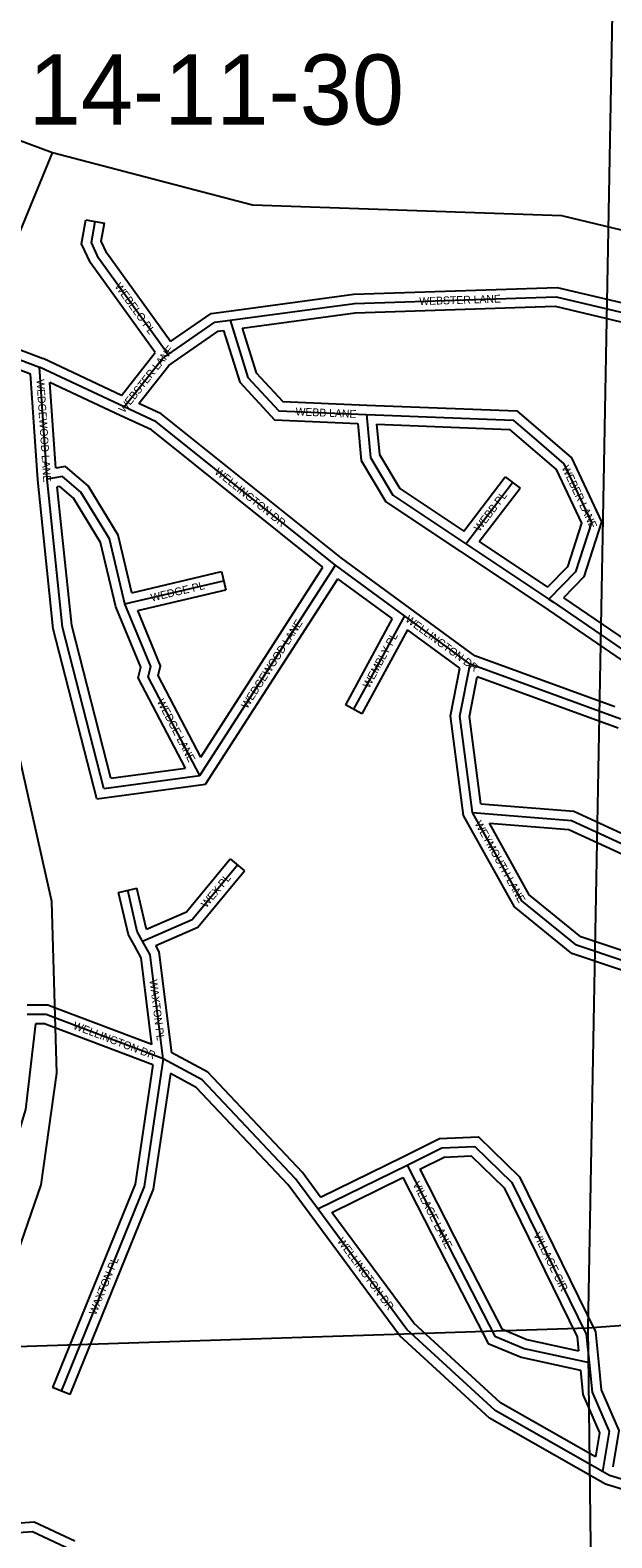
# Model space of a CAD drawing. Extents: x 457167 to 656239, y 1787309 to 1969297.
# Drawn here: x 578066 to 579932, y 1892149 to 1896984 of the extents above; entities that cross this region are included whole.
import ezdxf

# ---------------------------------------------------------------- set-up
doc = ezdxf.new("R2010")
doc.units = 0
for name, color, linetype in [('Level 1', 7, 'Continuous'), ('Level 2', 7, 'Continuous'), ('Level 31', 7, 'Continuous'), ('Level 32', 7, 'Continuous'), ('Level 34', 7, 'Continuous'), ('Level 5', 7, 'Continuous')]:
    doc.layers.add(name, color=color, linetype=linetype)

msp = doc.modelspace()

# ---------------------------------------------------------------- linework, layer by layer
at = {"layer": 'Level 1'}
for p, q in [((579953.491, 1898090.679), (579855.256, 1892821.831)), ((579855.256, 1892821.831), (585080.121, 1893221.401)), ((576739.189, 1892721.021), (579855.256, 1892821.831)), ((579855.256, 1892821.831), (579922.889, 1887536.016))]:
    msp.add_line(p, q, dxfattribs=at)
at = {"layer": 'Level 31'}
for p, q in [((578120.434, 1895544.188), (578096.068, 1895902.789)), ((578367.986, 1895775.306), (578096.068, 1895902.789)), ((579463.774, 1895336.65), (579613.948, 1895533.068)), ((579463.774, 1895336.65), (579730.51, 1895159.004)), ((578610.677, 1894593.328), (579045.49, 1895267.7)), ((579266.785, 1895105.419), (579045.49, 1895267.7)), ((578369.843, 1895143.658), (578686.706, 1895218.266)), ((579730.51, 1895159.004), (579744.799, 1895149.156)), ((579744.799, 1895149.156), (580021.054, 1894960.221)), ((579266.785, 1895105.419), (579103.994, 1894806.118)), ((579478.24, 1894950.432), (579266.785, 1895105.419)), ((579961.529, 1894774.523), (579478.24, 1894950.432)), ((578302.145, 1894552.157), (578610.677, 1894593.328)), ((578492.713, 1893684.837), (578145.742, 1893816.477)), ((578988.735, 1893203.794), (579275.224, 1893344.291))]:
    msp.add_line(p, q, dxfattribs=at)
for points in [[(578509.2, 1895943.375), (578285.678, 1896252.94), (578262.571, 1896302.807), (578274.795, 1896370.419)], [(578707.526, 1896053.143), (579106.694, 1896107.583), (579753.809, 1896128.422), (579980.414, 1896074.863)], [(578509.2, 1895943.375), (578658.228, 1896046.7), (578707.526, 1896053.143)], [(578707.526, 1896053.143), (578765.015, 1895869.747), (578863.684, 1895762.994), (579144.749, 1895751.499)], [(577895.856, 1895955.577), (577962.624, 1895952.89), (578096.068, 1895902.789)], [(578367.986, 1895775.306), (578490.414, 1895930.687), (578509.2, 1895943.375)], [(579045.49, 1895267.7), (578470.909, 1895727.09), (578367.986, 1895775.306)], [(579144.749, 1895751.499), (579615.631, 1895733.067), (579698.476, 1895661.986)], [(579144.749, 1895751.499), (579157.818, 1895613.652), (579230.065, 1895492.41), (579463.774, 1895336.65)], [(579698.476, 1895661.986), (579778.465, 1895593.456), (579867.429, 1895404.543), (579816.228, 1895246.465), (579730.51, 1895159.004)], [(578369.843, 1895143.658), (578320.357, 1895352.128), (578228.776, 1895502.505), (578170.374, 1895552.446), (578120.434, 1895544.188)], [(578302.145, 1894552.157), (578169.677, 1895069.17), (578120.434, 1895544.188)], [(578610.677, 1894593.328), (578444.398, 1894910.408), (578453.053, 1894943.481), (578369.843, 1895143.658)], [(579485.844, 1894475.139), (579444.826, 1894783.591), (579478.24, 1894950.432)], [(579485.844, 1894475.139), (579802.505, 1894449.393), (580094.143, 1894315.7), (580192.375, 1894303.134)], [(580702.275, 1894072.271), (580518.912, 1893973.371), (580385.289, 1893940.189), (580118.513, 1893948.736), (579818.537, 1894049.355), (579643.935, 1894191.536), (579485.844, 1894475.139)], [(578426.725, 1894062.798), (578585.864, 1894131.92), (578730.914, 1894306.891)], [(578426.725, 1894062.798), (578409.936, 1894093.38), (578379.049, 1894225.446)], [(578492.713, 1893684.837), (578451.436, 1894018.382), (578426.725, 1894062.798)], [(578145.742, 1893816.477), (578117.78, 1893827.082), (578056.09, 1893827.212)], [(578492.713, 1893684.837), (578431.755, 1893275.506), (578165.488, 1892619.696)], [(578988.735, 1893203.794), (578917.07, 1893300.672), (578617.544, 1893617.666), (578492.713, 1893684.837)], [(579275.224, 1893344.291), (579387.272, 1893399.331), (579492.539, 1893404.204), (579611.548, 1893288.683), (579850.317, 1892801.639), (579859.67, 1892710.711)], [(579275.224, 1893344.291), (579427.883, 1893046.516), (579557.425, 1892795.335), (579650.838, 1892756.596), (579859.67, 1892710.711)], [(579902.519, 1892361.164), (579557.889, 1892557.514), (579274.768, 1892816.649), (578988.735, 1893203.794)], [(579859.67, 1892710.711), (579869.017, 1892616.508), (579923.452, 1892489.486), (579902.519, 1892361.164)], [(580224.125, 1892256.501), (579924.435, 1892348.755), (579902.519, 1892361.164)], [(578196.539, 1892110.896), (578073.273, 1892168.248), (577614.957, 1892135.4)]]:
    msp.add_lwpolyline(points, dxfattribs=at)
at = {"layer": 'Level 32'}
for p, q in [((578245.274, 1896375.757), (578304.318, 1896365.081)), ((578359.16, 1895812.578), (578107.726, 1895930.456)), ((578359.161, 1895812.578), (578467.424, 1895949.985)), ((578090.539, 1895541.623), (578067.446, 1895881.489)), ((578148.128, 1895579.175), (578129.453, 1895854.002)), ((578355.253, 1895748.142), (578129.453, 1895854.002)), ((579457.019, 1895377.205), (579590.115, 1895551.29)), ((579590.115, 1895551.29), (579637.78, 1895514.846)), ((579507.059, 1895343.867), (579637.78, 1895514.846)), ((579507.059, 1895343.867), (579726.469, 1895197.741)), ((579447.145, 1895311.679), (579713.882, 1895134.033)), ((578392.117, 1895179.722), (578679.831, 1895247.468)), ((578613.349, 1894652.831), (579005.595, 1895261.186)), ((578679.831, 1895247.468), (578693.583, 1895189.064)), ((579284.527, 1895129.611), (579063.736, 1895291.521)), ((578628.382, 1894565.423), (579053.44, 1895224.666)), ((579227.907, 1895096.726), (579053.44, 1895224.666)), ((578411.105, 1895122.552), (578693.583, 1895189.064)), ((579776.944, 1895163.518), (580004.732, 1895007.73)), ((579492.523, 1894977.159), (579284.52, 1895129.615)), ((579713.882, 1895134.033), (579727.775, 1895124.454)), ((579727.864, 1895124.392), (579985.66, 1894948.082)), ((579227.907, 1895096.726), (579077.64, 1894820.452)), ((579276.739, 1895060.926), (579130.349, 1894791.783)), ((579445.065, 1894937.552), (579276.739, 1895060.927)), ((579942.484, 1894813.381), (579492.524, 1894977.159)), ((579953.204, 1894745.626), (579500.799, 1894910.295)), ((579130.349, 1894791.783), (579077.64, 1894820.452)), ((578324.593, 1894585.418), (578564.184, 1894617.389)), ((578279.699, 1894518.894), (578628.382, 1894565.423)), ((578707.818, 1894326.038), (578754.01, 1894287.744)), ((578349.838, 1894218.614), (578408.261, 1894232.278)), ((578456.829, 1893730.538), (578156.384, 1893844.526)), ((578459.481, 1893665.357), (578135.1, 1893788.427)), ((578997.982, 1893241.741), (579262.014, 1893371.226)), ((579034.237, 1893192.693), (579261.973, 1893304.376)), ((578193.284, 1892608.41), (578137.691, 1892630.981))]:
    msp.add_line(p, q, dxfattribs=at)
for points in [[(578467.424, 1895949.985), (578259.669, 1896237.712), (578231.361, 1896298.806), (578245.274, 1896375.757)], [(578516.294, 1895984.798), (578311.688, 1896268.166), (578293.782, 1896306.809), (578304.318, 1896365.081)], [(578703.472, 1896082.868), (579104.178, 1896137.518), (579756.829, 1896158.536), (579999.101, 1896101.273)], [(578516.294, 1895984.798), (578647.119, 1896075.504), (578703.639, 1896082.89)], [(578746.781, 1896028.217), (579109.212, 1896077.648), (579750.79, 1896098.309), (579961.728, 1896048.451)], [(578526.294, 1895918.72), (578669.336, 1896017.896), (578686.436, 1896020.13)], [(578686.436, 1896020.131), (578738.406, 1895854.337), (578850.069, 1895733.525), (579117.354, 1895722.593)], [(578746.78, 1896028.216), (578791.625, 1895885.156), (578877.298, 1895792.463), (579145.974, 1895781.474)], [(577897.062, 1895985.554), (577968.651, 1895982.672), (578107.727, 1895930.456)], [(577894.649, 1895925.601), (577956.597, 1895923.107), (578067.447, 1895881.49)], [(578414.949, 1895786.434), (578511.083, 1895908.444), (578526.294, 1895918.72)], [(579063.735, 1895291.521), (578486.862, 1895752.746), (578414.95, 1895786.433)], [(579145.922, 1895781.476), (579627.24, 1895762.636), (579718.011, 1895684.754)], [(579005.595, 1895261.186), (578454.957, 1895701.433), (578355.26, 1895748.139)], [(579117.354, 1895722.592), (579128.589, 1895604.096), (579207.773, 1895471.214), (579447.137, 1895311.686)], [(579177.854, 1895720.178), (579604.023, 1895703.498), (579678.941, 1895639.218)], [(579177.854, 1895720.178), (579187.046, 1895623.207), (579252.358, 1895513.605), (579457.019, 1895377.205)], [(579717.994, 1895684.769), (579802.867, 1895612.055), (579899.625, 1895406.588), (579842.593, 1895230.506), (579776.944, 1895163.518)], [(579678.958, 1895639.203), (579754.064, 1895574.856), (579835.231, 1895402.498), (579789.862, 1895262.423), (579726.469, 1895197.74)], [(578392.116, 1895179.723), (578348.45, 1895363.676), (578251.91, 1895522.196), (578179.258, 1895584.324), (578148.128, 1895579.174)], [(578279.699, 1894518.894), (578140.065, 1895063.871), (578090.539, 1895541.623)], [(578341.214, 1895134.376), (578292.264, 1895340.579), (578205.642, 1895482.813), (578161.49, 1895520.569), (578153.187, 1895519.196)], [(578324.593, 1894585.418), (578199.289, 1895074.468), (578153.188, 1895519.196)], [(578564.184, 1894617.39), (578412.434, 1894906.765), (578421.47, 1894941.298), (578341.214, 1895134.376)], [(578613.349, 1894652.831), (578476.363, 1894914.051), (578484.634, 1894945.663), (578411.106, 1895122.551)], [(579456.86, 1894465.52), (579414.429, 1894784.586), (579445.065, 1894937.552)], [(579512.394, 1894503.08), (579475.223, 1894782.596), (579500.799, 1894910.294)], [(579512.394, 1894503.079), (579810.204, 1894478.867), (580102.486, 1894344.878), (580172.647, 1894335.902)], [(580729.723, 1894052.986), (580529.819, 1893945.167), (580388.484, 1893910.071), (580113.149, 1893918.893), (579803.824, 1894022.647), (579620.532, 1894171.905), (579456.86, 1894465.52)], [(579539.398, 1894440.684), (579794.807, 1894419.919), (580085.799, 1894286.521), (580188.569, 1894273.376)], [(580674.829, 1894091.552), (580508.005, 1894001.573), (580382.094, 1893970.307), (580123.877, 1893978.581), (579833.249, 1894076.063), (579667.339, 1894211.167), (579539.398, 1894440.684)], [(578439.861, 1894101.211), (578567.34, 1894156.583), (578707.818, 1894326.038)], [(578469.031, 1894048.464), (578604.389, 1894107.257), (578754.01, 1894287.744)], [(578439.861, 1894101.211), (578438.212, 1894104.214), (578408.261, 1894232.278)], [(578400.428, 1894048.361), (578381.659, 1894082.546), (578349.838, 1894218.614)], [(578456.828, 1893730.539), (578422.379, 1894008.901), (578400.509, 1894048.213)], [(578520.583, 1893703.907), (578480.492, 1894027.863), (578469.031, 1894048.464)], [(578156.38, 1893844.528), (578123.309, 1893857.071), (578056.154, 1893857.213)], [(578082.804, 1893797.154), (578050.933, 1893522.652), (578002.139, 1893359.858)], [(578135.103, 1893788.426), (578112.252, 1893797.093), (578082.804, 1893797.155)], [(578997.981, 1893241.741), (578940.115, 1893319.966), (578636.024, 1893641.79), (578520.583, 1893703.907)], [(578459.481, 1893665.357), (578402.609, 1893283.471), (578137.691, 1892630.981)], [(578516.098, 1893638.185), (578460.901, 1893267.541), (578193.284, 1892608.41)], [(578964.617, 1893185.952), (578894.025, 1893281.379), (578599.064, 1893593.542), (578516.098, 1893638.185)], [(579261.996, 1893371.217), (579379.648, 1893429.011), (579504.119, 1893434.773), (579636.188, 1893306.576), (579879.612, 1892810.036), (579889.513, 1892713.78)], [(579315.844, 1893330.818), (579394.895, 1893369.651), (579480.958, 1893373.635), (579586.908, 1893270.791), (579821.022, 1892793.242), (579825.581, 1892748.916)], [(579315.844, 1893330.818), (579454.563, 1893060.234), (579579.057, 1892818.842), (579659.874, 1892785.327), (579825.581, 1892748.916)], [(579261.973, 1893304.376), (579401.203, 1893032.796), (579535.794, 1892771.828), (579641.803, 1892727.866), (579831.968, 1892686.081)], [(579887.668, 1892335.097), (579540.115, 1892533.112), (579252.367, 1892796.483), (578964.606, 1893185.966)], [(579879.861, 1892408.601), (579575.664, 1892581.915), (579297.169, 1892836.816), (579034.237, 1893192.693)], [(579831.967, 1892686.081), (579839.62, 1892608.943), (579892.437, 1892485.696), (579879.861, 1892408.601)], [(579889.524, 1892713.672), (579898.414, 1892624.074), (579954.468, 1892493.275), (579935.494, 1892376.969)], [(580192.379, 1892234.883), (579912.493, 1892321.041), (579887.738, 1892335.057)], [(578209.193, 1892138.097), (578078.88, 1892198.728), (577631.747, 1892166.68)]]:
    msp.add_lwpolyline(points, dxfattribs=at)
at = {"layer": 'Level 5'}
for points in [[(578138.009, 1896589.983), (577213.032, 1896932.786), (576748.308, 1896983.071)], [(576740.565, 1891623.016), (577149.298, 1891880.984), (577708.418, 1892430.6), (577950.616, 1892847.151), (578101.122, 1893280.483), (578151.529, 1893638.911), (578135.441, 1894189.115), (577861.641, 1895406.513), (577870.307, 1895706.62), (577903.974, 1896023.368), (578138.009, 1896589.983)], [(584831.26, 1895849.23), (584764.372, 1895682.606), (584505.692, 1895416.097), (584288.751, 1895249.602), (584163.64, 1895191.381), (583905.246, 1895208.339), (582955.14, 1895434.44), (582579.975, 1895409.817), (582438.224, 1895359.966), (582254.565, 1895126.739), (582120.867, 1894810.091), (582012.368, 1894693.517), (581912.326, 1894693.616), (581737.333, 1894768.837), (581254.577, 1895461.241), (580963.159, 1895786.688), (580654.941, 1896028.772), (580155.06, 1896296.056), (579771.684, 1896388.176), (578779.7, 1896422.572), (578138.009, 1896589.983)]]:
    msp.add_lwpolyline(points, dxfattribs=at)

# ---------------------------------------------------------------- texts
at = {"layer": 'Level 2'}
msp.add_text('14-11-30', height=225, dxfattribs=at).set_placement((578061.214, 1896680.654))
at = {"layer": 'Level 34'}
for s, height, rotation, p in [('WEBELO PL', 25, 305.830947, (578335.864, 1896162.083)), ('WEBSTER LANE', 25, 1.844222, (579314.966, 1896101.784)), ('WEBSTER LANE', 25, 51.763992, (578367.381, 1895754.344)), ('WEDGEWOOD LANE', 25, 273.886464, (578086.237, 1895863.106)), ('WEBB LANE', 25, 357.657675, (578917.321, 1895748.291)), ('WELLINGTON DR', 25, 321.356747, (578655.929, 1895563.158)), ('WEBER LANE', 25, 295.216314, (579770.779, 1895580.441)), ('WEBB PL', 25, 52.599275, (579507.757, 1895373.597)), ('WEDGE PL', 25, 13.249078, (578456.181, 1895151.146)), ('WELLINGTON DR', 25, 323.760231, (579267.575, 1895089.342)), ('WEDGEWOOD LANE', 25, 57.186489, (578762.294, 1894805.417)), ('WEMBLY PL', 25, 61.457192, (579153.706, 1894871.357)), ('WEDGE LANE', 24.9992, 297.672367, (578471.929, 1894830.996)), ('WEYMOUTH LANE', 25, 299.136483, (579491.174, 1894439.907)), ('WEX PL', 25, 50.340664, (578631.227, 1894167.055)), ('WAXTON PL', 24.9992, 277.053989, (578448.82, 1893937.749)), ('WELLINGTON DR', 25, 339.223167, (578201.713, 1893781.874)), ('VILLAGE LANE', 25, 297.142228, (579292.368, 1893283.453)), ('VILLAGE CIR', 25, 296.115525, (579679.573, 1893121.531)), ('WELLINGTON DR', 25, 306.457544, (579049.829, 1893100.069)), ('WAXTON PL', 25, 67.901314, (578276.968, 1892861.041))]:
    msp.add_text(s, height=height, rotation=rotation, dxfattribs=at).set_placement(p)

doc.saveas('drawing.dxf')
